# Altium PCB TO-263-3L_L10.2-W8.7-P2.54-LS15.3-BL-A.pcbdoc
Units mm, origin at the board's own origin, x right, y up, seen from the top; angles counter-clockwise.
Board outline 23.3 x 30.17 mm, 2 copper layers (Top Layer, Bottom Layer), stack 0 mm thick; 1 components, 0 nets, 4 pads, 0 vias.
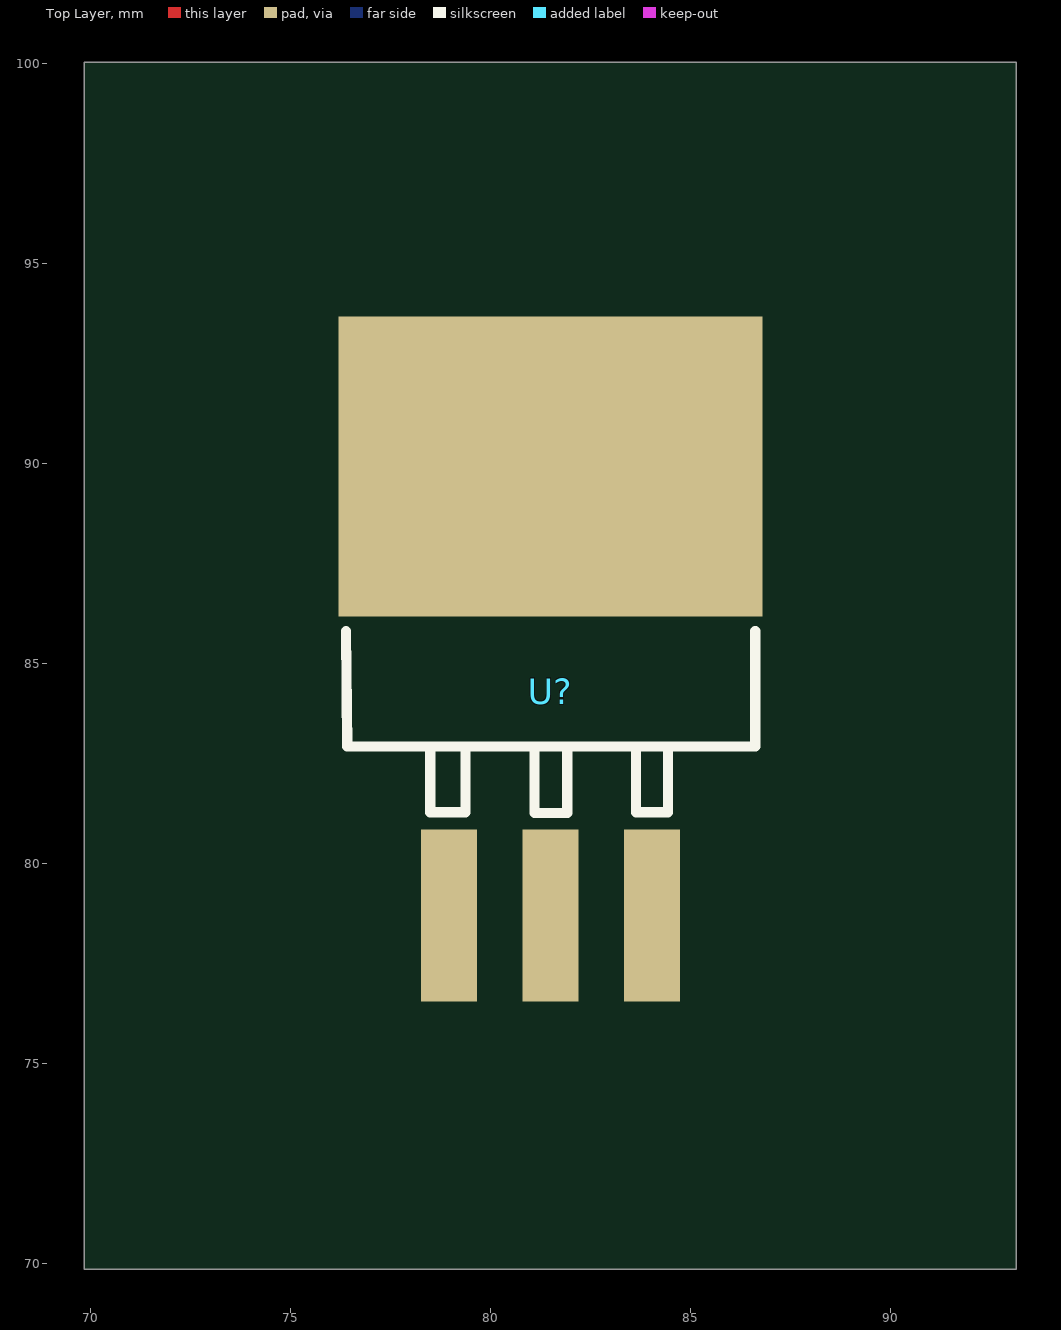
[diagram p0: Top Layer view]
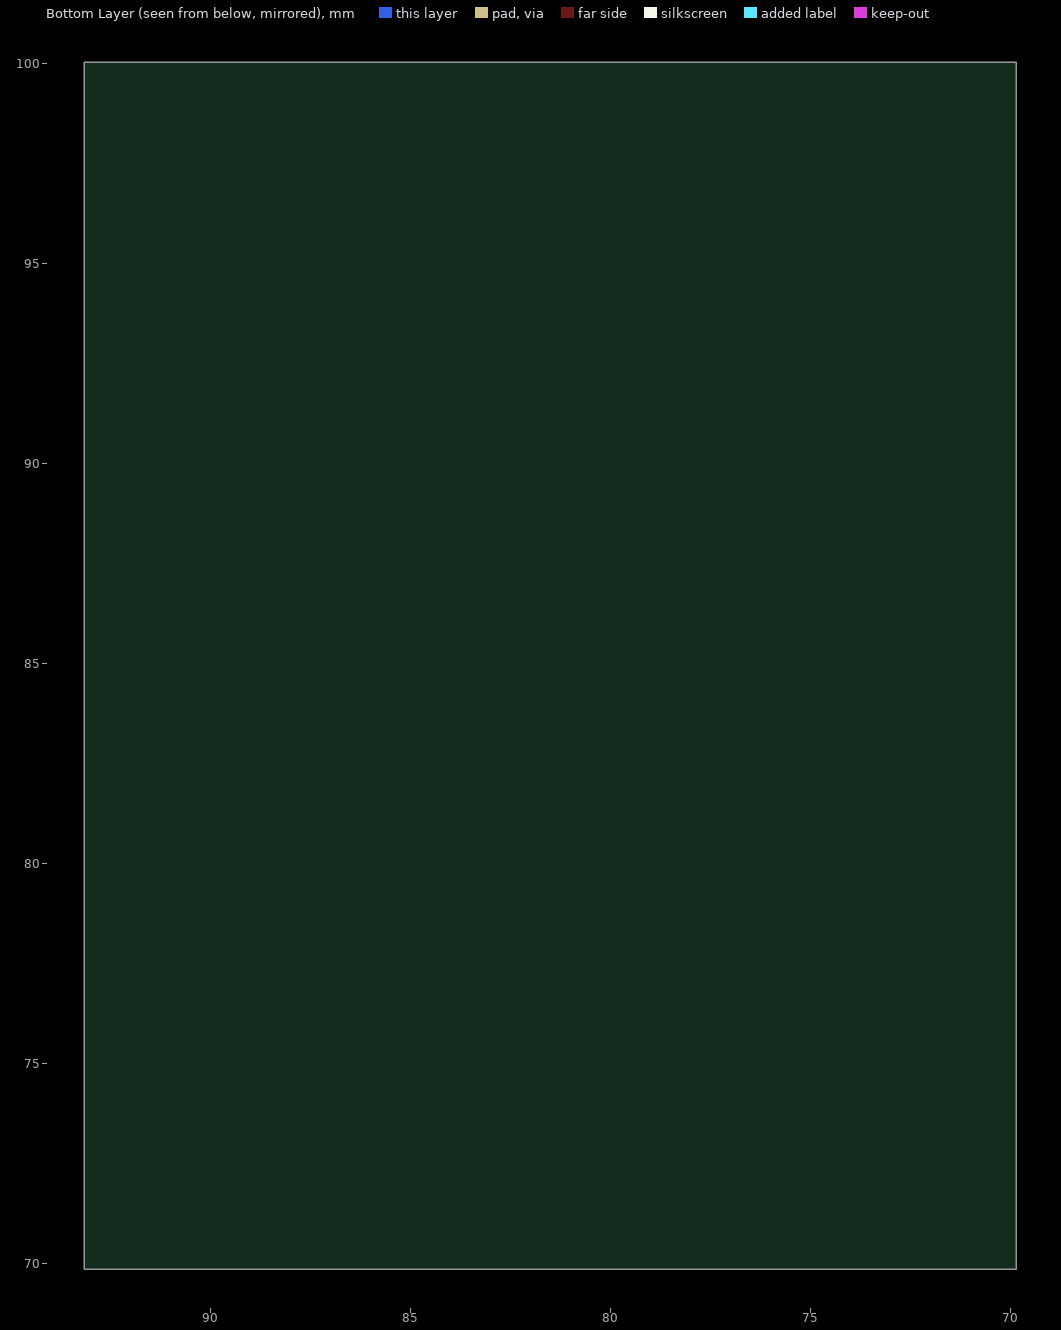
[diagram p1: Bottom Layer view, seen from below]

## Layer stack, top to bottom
Top Layer: signal copper (thickness not stored)
Bottom Layer: signal copper (thickness not stored)

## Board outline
93.15,69.85 69.85,69.85 69.85,100.024 93.15,100.024

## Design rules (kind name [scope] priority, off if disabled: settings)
PasteMaskExpansion "Paste Mask Expansion" [All] p1: expansion=0
SolderMaskExpansion "Solder Mask Expansion" [IsVia] p1: expansion=-25.4 istentingtop=TRUE
SolderMaskExpansion "Solder Mask Expansion" [All] p2: expansion=0.051 istentingtop=FALSE

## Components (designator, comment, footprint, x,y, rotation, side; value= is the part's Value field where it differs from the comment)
U? "" TO-263-3L_L10.2-W8.7-P2.54-LS15.3-BL-A 81.5,84.31 r0 top

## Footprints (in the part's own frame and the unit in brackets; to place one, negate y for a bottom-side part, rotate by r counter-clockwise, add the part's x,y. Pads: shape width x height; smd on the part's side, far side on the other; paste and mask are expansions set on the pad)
TO-263-3L_L10.2-W8.7-P2.54-LS15.3-BL-A [mm]
  rect 1.4x4.3 smd: 1(-2.54,-5.615) 2(0,-5.615) 3(2.54,-5.615)
  rect 10.6x7.5 smd paste+0 mask+0.05: 4(0,5.615)
  silkscreen extent -5.11,-3.05 5.12,1.5

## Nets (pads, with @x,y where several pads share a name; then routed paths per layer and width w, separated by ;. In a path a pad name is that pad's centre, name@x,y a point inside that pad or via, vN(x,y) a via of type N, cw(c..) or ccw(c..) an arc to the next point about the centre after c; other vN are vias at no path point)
pads on no net: U?.1 U?.2 U?.3 U?.4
